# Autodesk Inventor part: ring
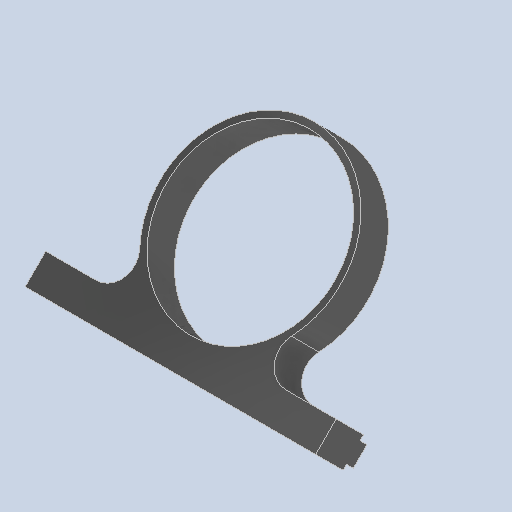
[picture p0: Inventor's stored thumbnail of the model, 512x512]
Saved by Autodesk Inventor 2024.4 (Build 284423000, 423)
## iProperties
Created: 2025-04
Part Number: ring
Material: Generic
Document SubType Name: Modeling
Designer: AdminForWorker
Density: 1 g/cm^3
Appearance: Default
Title: ring v1
Author: AdminForWorker
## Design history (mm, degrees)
feature "Body2"
body "Solid1"
